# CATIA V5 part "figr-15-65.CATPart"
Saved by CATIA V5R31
Part number: Part1
Bounding box of the stored display mesh (mm): x -92.936 to 49.742, y -31.904 to 31.904, z 0 to 63.808
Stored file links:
  D:\PROJECTS\Project 2021\US EDITION\CATIA V5 6R 2021\Resources\Part Files\c15_catia_v5_6r2021_prt\figr-15-65.CATPart
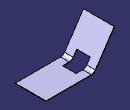
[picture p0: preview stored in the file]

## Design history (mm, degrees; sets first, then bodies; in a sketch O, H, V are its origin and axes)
SheetMetalParameters1: Thickness 1, BendRadius 10, KFactor 0.5 {= log(min(100,max(20*SheetMetalParameters1.BendRadius,SheetMetalParameters1.Thickness)/SheetMetalParameters1.Thickness))/log(100)/2}, ReliefRadialLength 1, ReliefAxialLength 2, MinimumBendRadius 0
Body1 (main body)
  Sketch1 on xy-plane, origin (0, 0, 0), H (1, 0, 0), V (0, 1, 0)
    line L1 (49.7419, 31.9042) -> (49.7419, -31.9042)
    line L2 (49.7419, -31.9042) -> (-49.7419, -31.9042)
    line L3 (-49.7419, -31.9042) -> (-49.7419, 31.9042)
    line L4 (-49.7419, 31.9042) -> (49.7419, 31.9042)
    vertical: L1 V, L3 V
    horizontal: L2 H, L4 H
    equidistance: L1 L3 O, L2 L4 O
  Wall1: Thickness 1, Profile Sketch1
  d_NewWallOnEdge1: NewWallOnEdge_Edge edge [face of Wall1 | face of Wall1], NewWallOnEdge_Length 63.8083, NewWallOnEdge_HeightLimitOffset 0, NewWallOnEdge_WidthOffset1 0, NewWallOnEdge_WidthOffset2 0, NewWallOnEdge_Angle 124, NewWallOnEdge_BendRadiusValue 10 {= SheetMetalParameters1.BendRadius}, NewWallOnEdge_BendTable SheetMetalParameters1, KFacteur 0.5 {= log(min(100,max(20*d_NewWallOnEdge1.Radius,SheetMetalParameters1.Thickness)/SheetMetalParameters1.Thickness))/log(100)/2}
  Sketch2 on face of d_NewWallOnEdge1, origin (0, 0, 1), H (1, 0, 0), V (0, 1, 0)
    point P1 (-49.1841, 0)
    line L1 (-30.5497, 14.1437) -> (-30.5497, -14.1437)
    line L2 (-30.5497, -14.1437) -> (-67.8185, -14.1437)
    line L3 (-67.8185, -14.1437) -> (-67.8185, 14.1437)
    line L4 (-67.8185, 14.1437) -> (-30.5497, 14.1437)
    coincidence: P1 H
    vertical: L1 V, L3 V
    horizontal: L2 H, L4 H
    equidistance: L1 L3 P1, L2 L4 P1
  CutOut1: Direction Sketch2, EndLimit through (limit type 2), Orientation true, Profile Sketch2, StartLimit through (limit type 2)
